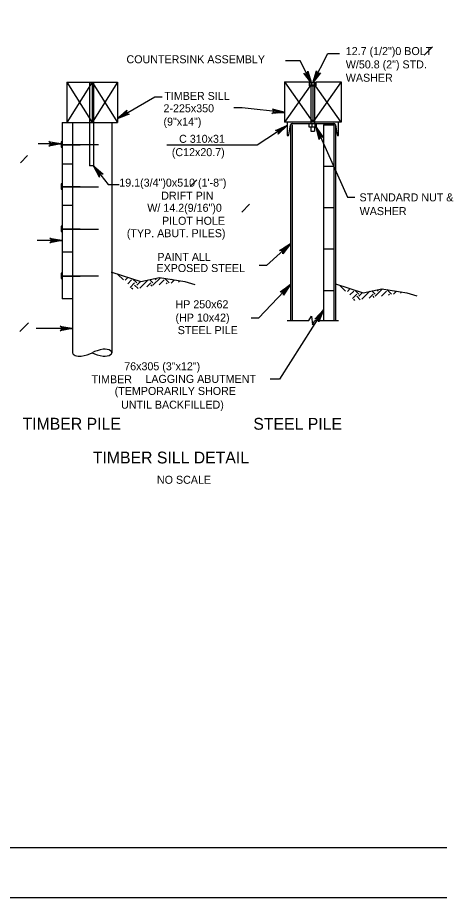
# Model space of a CAD drawing. Extents: x -8 to 75, y -110 to 0.
# Drawn here: x 52.74 to 59.07, y -88 to -74.81 of the extents above; entities that cross this region are included whole.
import ezdxf

# ---------------------------------------------------------------- set-up
doc = ezdxf.new("R2010")
doc.units = 0
for name, color, linetype in [('1', 7, 'Continuous'), ('2', 7, 'Continuous'), ('3', 7, 'Continuous'), ('63', 7, 'Continuous')]:
    doc.layers.add(name, color=color, linetype=linetype)

msp = doc.modelspace()

# ---------------------------------------------------------------- linework, layer by layer
at = {"layer": '1'}
msp.add_lwpolyline([(35.75, -87.25), (67.25, -87.25), (67.25, -66.75), (35.75, -66.75)], close=True, dxfattribs=at)
at = {"layer": '2'}
for p, q in [((53.481, -75.774), (53.859, -76.379)), ((53.859, -75.774), (53.481, -76.379)), ((53.481, -75.774), (53.481, -76.379)), ((53.481, -75.774), (54.237, -75.774)), ((53.82, -75.774), (53.82, -77.03)), ((53.859, -75.774), (53.859, -76.379)), ((54.237, -75.774), (53.859, -76.379)), ((53.859, -75.774), (54.237, -76.379)), ((53.878, -75.774), (53.878, -77.03)), ((54.237, -75.774), (54.237, -76.379)), ((56.745, -75.77), (56.745, -76.375)), ((56.745, -75.77), (57.171, -76.375)), ((56.745, -75.77), (57.116, -75.77)), ((56.745, -75.77), (56.9, -75.77)), ((57.13, -75.828), (56.745, -76.375)), ((57.116, -75.77), (57.116, -75.828)), ((57.116, -75.813), (57.221, -75.813)), ((57.127, -75.813), (57.127, -75.79)), ((57.198, -75.783), (57.137, -75.783)), ((57.139, -75.828), (57.139, -76.393)), ((57.148, -75.79), (57.148, -75.813)), ((57.597, -75.77), (57.171, -76.375)), ((57.171, -75.828), (57.171, -76.375)), ((57.188, -75.79), (57.188, -75.813)), ((57.197, -75.828), (57.197, -76.393)), ((57.207, -75.813), (57.207, -75.79)), ((57.597, -76.375), (57.212, -75.828)), ((57.221, -75.77), (57.597, -75.77)), ((57.597, -75.77), (57.597, -76.375)), ((54.237, -76.32), (54.8, -75.992)), ((54.8, -75.992), (54.911, -75.992)), ((53.41, -76.379), (53.41, -79.024)), ((53.41, -76.379), (53.565, -76.379)), ((53.481, -76.379), (54.237, -76.379)), ((53.565, -76.379), (53.565, -79.831)), ((54.153, -76.379), (54.153, -79.831)), ((57.597, -76.375), (56.745, -76.375)), ((56.787, -76.375), (56.787, -76.575)), ((56.859, -76.393), (57.484, -76.393)), ((57.16, -76.451), (57.16, -76.393)), ((57.203, -76.451), (57.203, -76.393)), ((57.556, -76.575), (57.556, -76.375)), ((56.808, -76.564), (56.833, -76.415)), ((56.833, -76.415), (56.833, -79.347)), ((56.858, -76.415), (56.858, -79.347)), ((57.139, -76.451), (57.139, -76.507)), ((57.139, -76.507), (57.197, -76.507)), ((57.197, -76.451), (57.197, -76.507)), ((57.33, -76.415), (57.33, -79.347)), ((57.33, -76.415), (57.485, -76.415)), ((57.485, -76.415), (57.485, -79.347)), ((57.51, -76.415), (57.51, -79.347)), ((57.51, -76.415), (57.535, -76.564)), ((56.787, -76.575), (56.795, -76.575)), ((57.548, -76.575), (57.556, -76.575)), ((53.411, -76.702), (53.956, -76.71)), ((53.411, -76.718), (53.956, -76.71)), ((53.41, -76.999), (53.565, -76.999)), ((53.878, -77.03), (53.82, -77.03)), ((57.33, -77.035), (57.485, -77.035)), ((53.411, -77.335), (53.956, -77.343)), ((53.411, -77.351), (53.956, -77.343)), ((53.41, -77.62), (53.565, -77.62)), ((57.33, -77.656), (57.485, -77.656)), ((53.411, -77.97), (53.956, -77.978)), ((53.411, -77.986), (53.956, -77.978)), ((56.833, -78.199), (56.473, -78.524)), ((53.565, -78.322), (53.41, -78.322)), ((57.33, -78.276), (57.485, -78.276)), ((56.473, -78.524), (56.362, -78.524)), ((53.411, -78.672), (53.956, -78.68)), ((53.411, -78.689), (53.956, -78.68)), ((54.328, -78.74), (54.241, -78.653)), ((54.356, -78.743), (54.396, -78.703)), ((54.393, -78.798), (54.45, -78.74)), ((54.527, -78.786), (54.465, -78.725)), ((54.527, -78.817), (54.582, -78.762)), ((54.573, -78.863), (54.693, -78.743)), ((54.771, -78.786), (54.722, -78.737)), ((54.771, -78.817), (54.882, -78.707)), ((54.817, -78.74), (54.797, -78.72)), ((54.865, -78.815), (54.94, -78.74)), ((55.016, -78.786), (54.947, -78.717)), ((55.045, -78.788), (55.093, -78.74)), ((55.062, -78.74), (55.056, -78.734)), ((55.152, -78.773), (55.172, -78.753)), ((54.43, -78.853), (54.496, -78.786)), ((54.469, -78.881), (54.45, -78.863)), ((54.547, -78.868), (54.496, -78.817)), ((54.681, -78.846), (54.741, -78.786)), ((54.757, -78.833), (54.741, -78.817)), ((54.974, -78.798), (54.986, -78.786)), ((57.33, -78.897), (57.485, -78.897)), ((57.661, -78.909), (57.574, -78.822)), ((57.689, -78.912), (57.73, -78.871)), ((57.86, -78.955), (57.798, -78.893)), ((58.105, -78.985), (58.215, -78.875)), ((58.151, -78.909), (58.13, -78.889)), ((58.349, -78.955), (58.28, -78.886)), ((53.565, -79.024), (53.41, -79.024)), ((57.726, -78.966), (57.783, -78.909)), ((57.763, -79.021), (57.829, -78.955)), ((57.802, -79.05), (57.783, -79.031)), ((57.881, -79.037), (57.829, -78.985)), ((57.86, -78.985), (57.915, -78.93)), ((57.906, -79.031), (58.026, -78.911)), ((58.015, -79.014), (58.074, -78.955)), ((58.105, -78.955), (58.055, -78.905)), ((58.09, -79.002), (58.074, -78.985)), ((58.198, -78.984), (58.273, -78.909)), ((58.307, -78.967), (58.319, -78.955)), ((58.378, -78.956), (58.426, -78.909)), ((58.395, -78.909), (58.389, -78.903)), ((58.485, -78.941), (58.505, -78.921)), ((57.111, -79.347), (57.15, -79.285)), ((57.15, -79.285), (57.163, -79.413)), ((56.787, -79.347), (57.111, -79.347)), ((57.163, -79.413), (57.199, -79.347)), ((57.199, -79.347), (57.555, -79.347))]:
    msp.add_line(p, q, dxfattribs=at)
for points in [[(57.116, -75.828), (57.221, -75.828), (57.221, -75.77)], [(54.143, -78.624), (54.153, -78.625), (54.591, -78.765), (54.87, -78.705), (55.248, -78.765), (55.397, -78.81)], [(57.51, -78.801), (57.924, -78.933), (58.203, -78.873), (58.581, -78.933), (58.73, -78.978)]]:
    msp.add_lwpolyline(points, dxfattribs=at)
for points in [[(54.342, -76.28), (54.323, -76.248), (54.237, -76.32)], [(57.116, -76.393), (57.221, -76.393), (57.221, -76.451), (57.116, -76.451)], [(53.395, -76.668), (53.395, -76.747), (53.411, -76.747), (53.411, -76.668)], [(53.395, -77.301), (53.395, -77.38), (53.411, -77.38), (53.411, -77.301)], [(53.395, -77.936), (53.395, -78.015), (53.411, -78.015), (53.411, -77.936)], [(56.739, -78.259), (56.763, -78.286), (56.833, -78.199)], [(53.395, -78.638), (53.395, -78.717), (53.411, -78.717), (53.411, -78.638)]]:
    msp.add_lwpolyline(points, close=True, dxfattribs=at)
for centre, radius, start, end in [((57.138, -75.795), 0.011, 88.1729, 158.7131), ((57.138, -75.795), 0.011, 21.2869, 88.1729), ((57.168, -75.815), 0.0316, 51.05, 128.95), ((57.197, -75.794), 0.0101, 17.4518, 162.5482), ((56.859, -76.419), 0.0262, 90.0372, 170.4628), ((57.484, -76.419), 0.0261, 9.5, 90), ((56.795, -76.562), 0.0131, 270.2863, 350.2137), ((57.548, -76.562), 0.0131, 189.5372, 269.9628)]:
    msp.add_arc(centre, radius, start, end, dxfattribs=at)
for centre, major_axis, start_param, end_param in [((54.153, -79.978), (0.416, 0), 1.89032, 2.356194), ((54.049, -79.831), (0.104, 0), 4.455588, 8.110783), ((53.669, -79.831), (-0.104, 0), 0, 1.827597), ((53.565, -79.684), (-0.416, 0), 1.89032, 2.356194), ((54.153, -79.684), (0.416, 0), 3.926991, 4.392865)]:
    msp.add_ellipse(centre, major_axis=major_axis, ratio=0.5, start_param=start_param, end_param=end_param, dxfattribs=at)
at = {"layer": '3'}
for p, q in [((58.838, -75.369), (58.966, -75.242)), ((56.979, -75.455), (56.76, -75.455)), ((57.397, -75.345), (57.571, -75.345)), ((56.108, -76.159), (55.985, -76.159)), ((56.745, -76.227), (56.108, -76.159)), ((56.787, -76.425), (56.335, -76.718)), ((56.335, -76.718), (54.979, -76.718)), ((52.783, -76.982), (52.89, -76.875)), ((53.878, -77.031), (54.097, -77.307)), ((54.097, -77.307), (54.263, -77.307)), ((55.33, -77.339), (55.431, -77.238)), ((57.691, -77.501), (57.802, -77.501)), ((56.102, -77.724), (56.22, -77.606)), ((56.833, -78.81), (56.353, -79.313)), ((57.33, -79.19), (56.669, -80.228)), ((52.775, -79.513), (52.905, -79.384)), ((56.353, -79.313), (56.242, -79.313)), ((56.669, -80.228), (56.532, -80.228))]:
    msp.add_line(p, q, dxfattribs=at)
for points in [[(57.148, -75.79), (56.979, -75.455)], [(57.168, -75.783), (57.397, -75.345)], [(57.148, -75.79), (57.033, -75.64), (57.048, -75.648), (57.063, -75.649), (57.075, -75.645), (57.085, -75.638), (57.093, -75.626), (57.096, -75.608), (57.148, -75.79), (57.093, -75.626), (57.085, -75.638), (57.148, -75.79), (57.075, -75.645), (57.063, -75.649), (57.148, -75.79), (57.048, -75.648)], [(57.168, -75.783), (57.223, -75.602), (57.226, -75.619), (57.233, -75.632), (57.243, -75.639), (57.255, -75.643), (57.27, -75.643), (57.285, -75.635), (57.168, -75.783), (57.27, -75.643), (57.255, -75.643), (57.168, -75.783), (57.243, -75.639), (57.233, -75.632), (57.168, -75.783), (57.226, -75.619)], [(54.237, -76.32), (54.38, -76.196), (54.373, -76.212), (54.373, -76.226), (54.377, -76.238), (54.386, -76.248), (54.398, -76.255), (54.416, -76.256), (54.237, -76.32), (54.398, -76.255), (54.386, -76.248), (54.237, -76.32), (54.377, -76.238), (54.373, -76.226), (54.237, -76.32), (54.373, -76.212)], [(56.745, -76.227), (56.556, -76.242), (56.571, -76.234), (56.58, -76.222), (56.583, -76.21), (56.583, -76.197), (56.577, -76.184), (56.563, -76.172), (56.745, -76.227), (56.577, -76.184), (56.583, -76.197), (56.745, -76.227), (56.583, -76.21), (56.58, -76.222), (56.745, -76.227), (56.571, -76.234)], [(56.787, -76.425), (56.65, -76.555), (56.656, -76.539), (56.656, -76.525), (56.651, -76.513), (56.642, -76.504), (56.629, -76.497), (56.612, -76.497), (56.787, -76.425), (56.629, -76.497), (56.642, -76.504), (56.787, -76.425), (56.651, -76.513), (56.656, -76.525), (56.787, -76.425), (56.656, -76.539)], [(57.221, -76.451), (57.691, -77.501)], [(57.221, -76.451), (57.329, -76.607), (57.314, -76.598), (57.299, -76.596), (57.287, -76.6), (57.277, -76.607), (57.268, -76.619), (57.265, -76.636), (57.221, -76.451), (57.268, -76.619), (57.277, -76.607), (57.221, -76.451), (57.287, -76.6), (57.299, -76.596), (57.221, -76.451), (57.314, -76.598)], [(53.395, -76.7), (53.047, -76.7)], [(53.395, -76.7), (53.208, -76.735), (53.222, -76.725), (53.23, -76.712), (53.232, -76.7), (53.23, -76.687), (53.222, -76.675), (53.208, -76.665), (53.395, -76.7), (53.222, -76.675), (53.23, -76.687), (53.395, -76.7), (53.232, -76.7), (53.23, -76.712), (53.395, -76.7), (53.222, -76.725)], [(53.878, -77.031), (54.022, -77.156), (54.005, -77.151), (53.991, -77.153), (53.98, -77.159), (53.971, -77.168), (53.966, -77.182), (53.967, -77.199), (53.878, -77.031), (53.966, -77.182), (53.971, -77.168), (53.878, -77.031), (53.98, -77.159), (53.991, -77.153), (53.878, -77.031), (54.005, -77.151)], [(53.41, -78.147), (53.032, -78.147)], [(53.41, -78.147), (53.224, -78.182), (53.238, -78.172), (53.246, -78.159), (53.248, -78.147), (53.246, -78.134), (53.238, -78.122), (53.224, -78.112), (53.41, -78.147), (53.238, -78.122), (53.246, -78.134), (53.41, -78.147), (53.248, -78.147), (53.246, -78.159), (53.41, -78.147), (53.238, -78.172)], [(56.833, -78.199), (56.718, -78.349), (56.722, -78.332), (56.719, -78.318), (56.712, -78.307), (56.703, -78.3), (56.689, -78.295), (56.671, -78.297), (56.833, -78.199), (56.689, -78.295), (56.703, -78.3), (56.833, -78.199), (56.712, -78.307), (56.719, -78.318), (56.833, -78.199), (56.722, -78.332)], [(56.833, -78.81), (56.73, -78.969), (56.732, -78.952), (56.728, -78.938), (56.721, -78.928), (56.71, -78.921), (56.696, -78.918), (56.679, -78.921), (56.833, -78.81), (56.696, -78.918), (56.71, -78.921), (56.833, -78.81), (56.721, -78.928), (56.728, -78.938), (56.833, -78.81), (56.732, -78.952)], [(57.33, -79.19), (57.259, -79.366), (57.258, -79.349), (57.252, -79.336), (57.242, -79.327), (57.231, -79.322), (57.216, -79.322), (57.2, -79.329), (57.33, -79.19), (57.216, -79.322), (57.231, -79.322), (57.33, -79.19), (57.242, -79.327), (57.252, -79.336), (57.33, -79.19), (57.258, -79.349)], [(53.565, -79.467), (53.017, -79.467)], [(53.565, -79.467), (53.379, -79.502), (53.393, -79.492), (53.401, -79.48), (53.403, -79.467), (53.401, -79.455), (53.393, -79.442), (53.379, -79.432), (53.565, -79.467), (53.393, -79.442), (53.401, -79.455), (53.565, -79.467), (53.403, -79.467), (53.401, -79.48), (53.565, -79.467), (53.393, -79.492)]]:
    msp.add_lwpolyline(points, dxfattribs=at)
for points in [[(56.647, -76.198), (56.644, -76.235), (56.756, -76.228)], [(56.684, -76.469), (56.704, -76.5), (56.787, -76.425)], [(56.743, -78.878), (56.77, -78.903), (56.833, -78.81)], [(57.255, -79.274), (57.286, -79.293), (57.33, -79.19)]]:
    msp.add_lwpolyline(points, close=True, dxfattribs=at)
at = {"layer": '63'}
msp.add_lwpolyline([(34, -88), (68, -88), (68, -66), (34, -66)], close=True, dxfattribs=at)

# ---------------------------------------------------------------- texts
at = {"layer": '3'}
for s, height, p in [('12.7 (1/2")0 BOLT', 0.12, (57.664, -75.368)), ('COUNTERSINK ASSEMBLY', 0.12, (54.374, -75.491)), ('W/50.8 (2") STD.', 0.12, (57.664, -75.568)), ('WASHER', 0.12, (57.664, -75.768)), ('TIMBER SILL', 0.12, (54.941, -76.041)), ('2-225x350', 0.12, (54.929, -76.226)), ('(9"x14")', 0.12, (54.929, -76.426)), ('C 310x31', 0.12, (55.163, -76.684)), ('(C12x20.7)', 0.12, (55.054, -76.884)), ('19.1(3/4")0x510 (1\'-8")', 0.12, (54.266, -77.341)), ('DRIFT PIN', 0.12, (54.895, -77.536)), ('STANDARD NUT &', 0.12, (57.87, -77.562)), ('W/ 14.2(9/16")0', 0.12, (54.686, -77.718)), ('WASHER', 0.12, (57.872, -77.768)), ('PILOT HOLE', 0.12, (54.907, -77.913)), ('(TYP. ABUT. PILES)', 0.12, (54.379, -78.099)), ('PAINT ALL', 0.12, (54.837, -78.455)), ('EXPOSED STEEL', 0.12, (54.823, -78.622)), ('HP 250x62', 0.12, (55.109, -79.165)), ('(HP 10x42)', 0.12, (55.109, -79.365)), ('STEEL PILE', 0.12, (55.143, -79.553)), ('76x305 (3"x12")', 0.12, (54.34, -80.095)), ('TIMBER', 0.12, (53.85, -80.29)), ('LAGGING ABUTMENT', 0.12, (54.658, -80.284)), ('(TEMPORARILY SHORE ', 0.12, (54.197, -80.465)), ('UNTIL BACKFILLED)', 0.12, (54.292, -80.671)), ('TIMBER PILE', 0.17717, (52.815, -80.985)), ('STEEL PILE', 0.1772, (56.277, -80.986)), ('TIMBER SILL DETAIL', 0.17717, (53.869, -81.492)), ('NO SCALE', 0.12, (54.831, -81.797))]:
    msp.add_text(s, height=height, dxfattribs=at).set_placement(p)

doc.saveas('drawing.dxf')
